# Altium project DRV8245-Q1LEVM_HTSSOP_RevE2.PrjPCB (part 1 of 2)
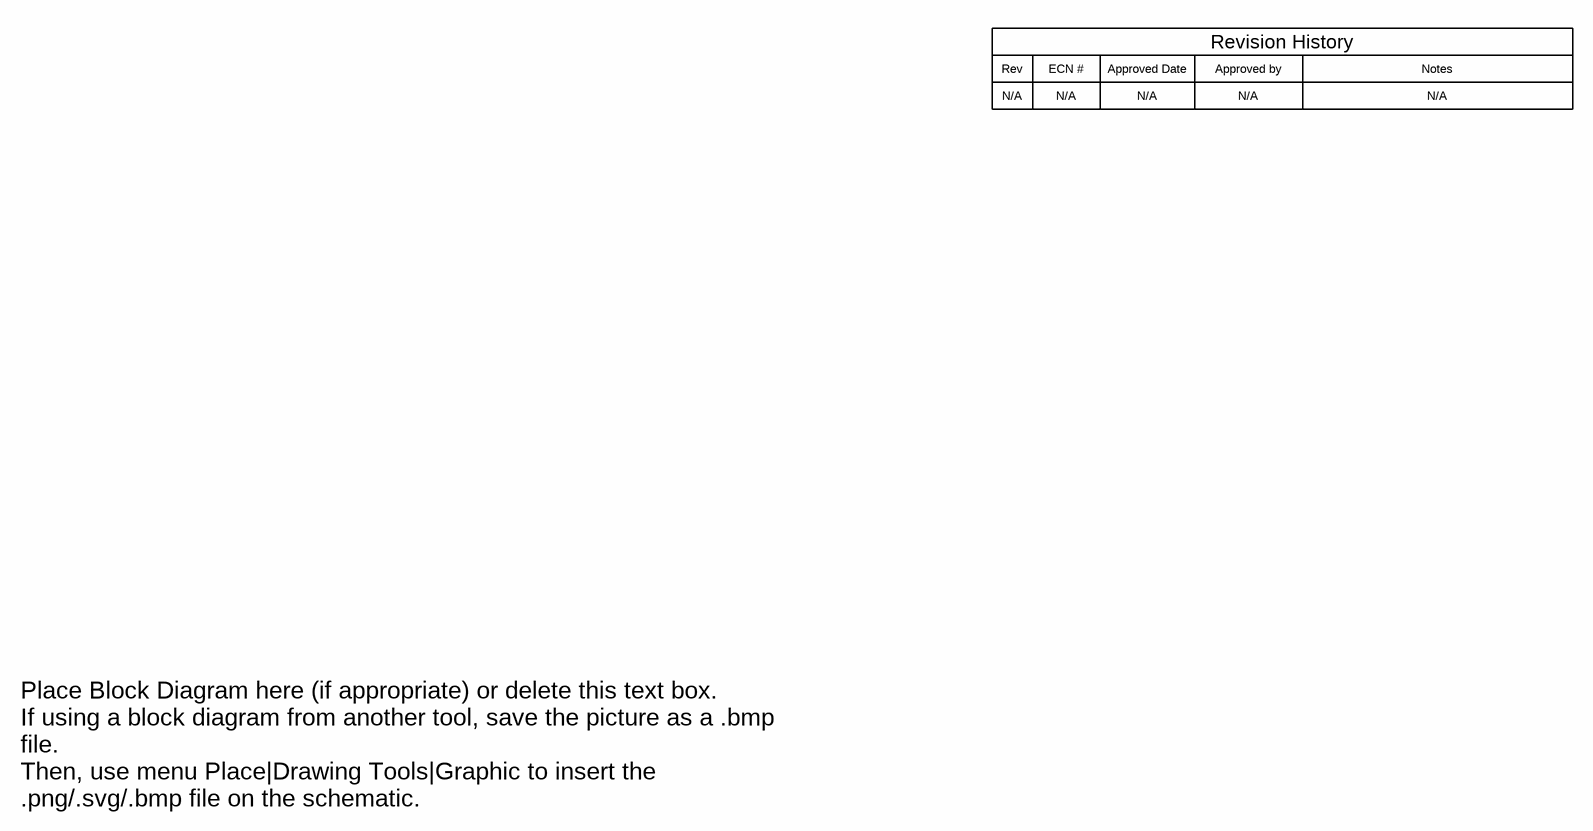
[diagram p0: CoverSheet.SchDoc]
CopyrightYear: 2020; PCB_Layout: Michael Erdahl; PCB_Rev: E2; PRJ_Customer: Public Release; PRJ_Engineer: Michael Erdahl; PRJ_Number: MD048; PRJ_Title: DRV8245S/H-Q1EVM HTSSOP; SCH_Rev: E2; TechSupport: http://www.ti.com/support; TID: N/A
4 sheets, 194 parts. Net scope: global (net labels, ports and power ports of the same name join across sheets).
Board file: DRV8245-Q1LEVM_HTSSOP_RevE2.PcbDoc
Sheets:
  CoverSheet.SchDoc
  Hardware.SchDoc
  DRV8245-Q1LEVM_HTSSOP_RevE2.SchDoc
  ezFET.SchDoc

## Sheet CoverSheet.SchDoc
size 431 x 279 mm; Date: Not shown in title block; ApprovedBy: Not shown in title block; CheckedBy: Not shown in title block; Author: Not shown in title block; CompanyName: Not shown in title block; Engineer: Not shown in title block; Organization: Not shown in title block; Address1: Not shown in title block; Address2: Not shown in title block; Address3: Not shown in title block; Address4: Not shown in title block; DocumentNumber: 1; Revision: Use project parameter SCH_Rev; SheetNumber: 1; SheetTotal: 3; PageSetup: Record=PageOptions¦CenterHorizontal=True¦CenterVertical=True¦PrintScale=1.00¦XCorrection=1.00¦YCorrection=1.00¦PrintKind=0¦BorderSize=5000000¦LeftOffset=0¦BottomOffset=0¦Orientation=2¦PaperLength=1000¦PaperWidth=1000¦Scale=100¦PaperSource=15¦PrintQuality=600¦MediaType=1¦DitherType=10¦PaperKind=Letter¦PrintScaleMode=1

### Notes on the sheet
- Rev
- N/A
- ECN #
- Approved Date
- Approved by
- Revision History
- Notes
- Place Block Diagram here (if appropriate) or delete this text box.
  If using a block diagram from another tool, save the picture as a .bmp file.
  Then, use menu Place|Drawing Tools|Graphic to insert the .png/.svg/.bmp file on the schematic.

## Sheet Hardware.SchDoc
size 431 x 279 mm; Date: Not shown in title block; ApprovedBy: Not shown in title block; CheckedBy: Not shown in title block; Author: Not shown in title block; CompanyName: Not shown in title block; Engineer: Not shown in title block; Organization: Not shown in title block; Address1: Not shown in title block; Address2: Not shown in title block; Address3: Not shown in title block; Address4: Not shown in title block; DocumentNumber: 3; Revision: Use project parameter SCH_Rev; SheetNumber: 3; SheetTotal: 3; PageSetup: Record=PageOptions¦CenterHorizontal=True¦CenterVertical=True¦PrintScale=1.00¦XCorrection=1.00¦YCorrection=1.00¦PrintKind=0¦BorderSize=5000000¦LeftOffset=0¦BottomOffset=0¦Orientation=2¦PaperLength=1000¦PaperWidth=1000¦Scale=100¦PaperSource=15¦PrintQuality=600¦MediaType=1¦DitherType=10¦PaperKind=Letter¦PrintScaleMode=1
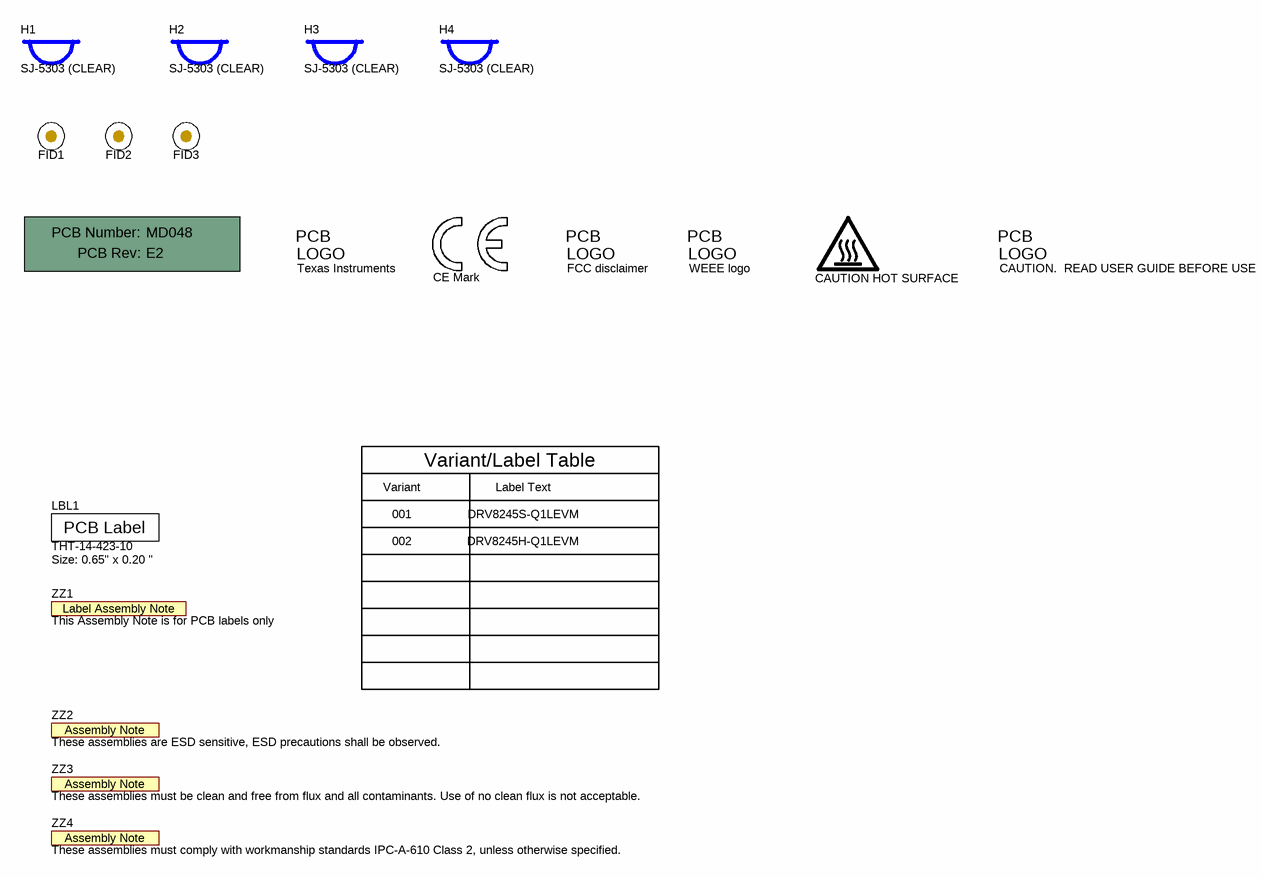
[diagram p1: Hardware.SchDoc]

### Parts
!PCB1  Printed Circuit Board  (value not drawn)  (mechanical)
FID1  Fiducial  [Fiducial10-20]  (value not drawn)
FID2  Fiducial  [Fiducial10-20]  (value not drawn)
FID3  Fiducial  [Fiducial10-20]  (value not drawn)
H1  SJ-5303 (CLEAR)  [Bumpon_SJ5003Transparent]
H2  SJ-5303 (CLEAR)  [Bumpon_SJ5003Transparent]
H3  SJ-5303 (CLEAR)  [Bumpon_SJ5003Transparent]
H4  SJ-5303 (CLEAR)  [Bumpon_SJ5003Transparent]
LBL1  THT-14-423-10  Note: Size: 0.65" x 0.20 "  [Label_650x200]
Logo1  CE Mark  [CE_Mark_5mm]  (no BOM)
Logo2  Texas Instruments  [TI_Stacked_Overlay_Small]  (no BOM)
Logo3  FCC disclaimer  [FCC_disclaimer]  (no BOM)
Logo4  WEEE logo  [WEEE_Minimum]  (no BOM)
Logo5  CAUTION.  READ USER GUIDE BEFORE USE  [IEC_Caution_Small]  (no BOM)
LOGO6  CAUTION HOT SURFACE  [IEC_HotSurface_Small]  (no BOM)
ZZ1  This Assembly Note is for PCB labels only  [AssemblyNoteLabel]  (no BOM)
ZZ2  These assemblies are ESD sensitive, ESD precautions shall be observed.  [AssemblyNote]  (no BOM)
ZZ3  These assemblies must be clean and free from flux and all contaminants. Use of no clean flux is not acceptable.  [AssemblyNote]  (no BOM)
ZZ4  These assemblies must comply with workmanship standards IPC-A-610 Class 2, unless otherwise specified.  [AssemblyNote]  (no BOM)

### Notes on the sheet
- Variant
- Variant/Label Table
- Label Text
- 001
- 002
- DRV8245S-Q1LEVM
- DRV8245H-Q1LEVM

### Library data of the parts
!PCB1 = CMP-0003618-2: Manufacturer: Any; PartNumber: MD048
FID1-FID3 = CMP-0077181-1: Fiducial mark.  There is nothing to buy or mount.
H1-H4 = CMP-0003620-1: Bumpon, Hemisphere, 0.44 X 0.20, Clear; Manufacturer: 3M
LBL1 = CMP-0003625-1: Thermal Transfer Printable Labels, 0.650" W x 0.200" H - 10,000 per roll; Manufacturer: Brady; CompType: Label
Logo1 = CMP-0074844-1: SymbolCreator: a0412235
Logo2 = CMP-0074838-1: Texas Instrument Corporate Signature; SymbolCreator: a0412235; Lib Reference: TI_Logo; Library Reference: Logo
Logo3 = CMP-0074847-1: FCC_disclaimer; Library Reference: Logo
Logo4 = CMP-0074769-1
Logo5 = CMP-0074836-1: IEC 61010-1 Caution Warning; SymbolCreator: a0412235; Lib Reference: IEC_Caution
LOGO6 = CMP-0074837-1: IEC 61010-1 Hot Surface Warning; SymbolCreator: a0412235
ZZ1 = CMP-0003616-3
ZZ2 = CMP-0077236-1
ZZ3 = CMP-0077237-1
ZZ4 = CMP-0077238-1

## Sheet DRV8245-Q1LEVM_HTSSOP_RevE2.SchDoc
size 431 x 279 mm; Date: Not shown in title block; ApprovedBy: Not shown in title block; CheckedBy: Not shown in title block; Author: Not shown in title block; CompanyName: Not shown in title block; Engineer: Not shown in title block; Organization: Not shown in title block; Address1: Not shown in title block; Address2: Not shown in title block; Address3: Not shown in title block; Address4: Not shown in title block; DocumentNumber: 2; Revision: Use project parameter SCH_Rev; SheetNumber: 2; SheetTotal: 3; PageSetup: Record=PageOptions¦CenterHorizontal=True¦CenterVertical=True¦PrintScale=1.00¦XCorrection=1.00¦YCorrection=1.00¦PrintKind=0¦BorderSize=5000000¦LeftOffset=0¦BottomOffset=0¦Orientation=2¦PaperLength=1000¦PaperWidth=1000¦Scale=100¦PaperSource=15¦PrintQuality=600¦MediaType=1¦DitherType=10¦PaperKind=Letter¦PrintScaleMode=1
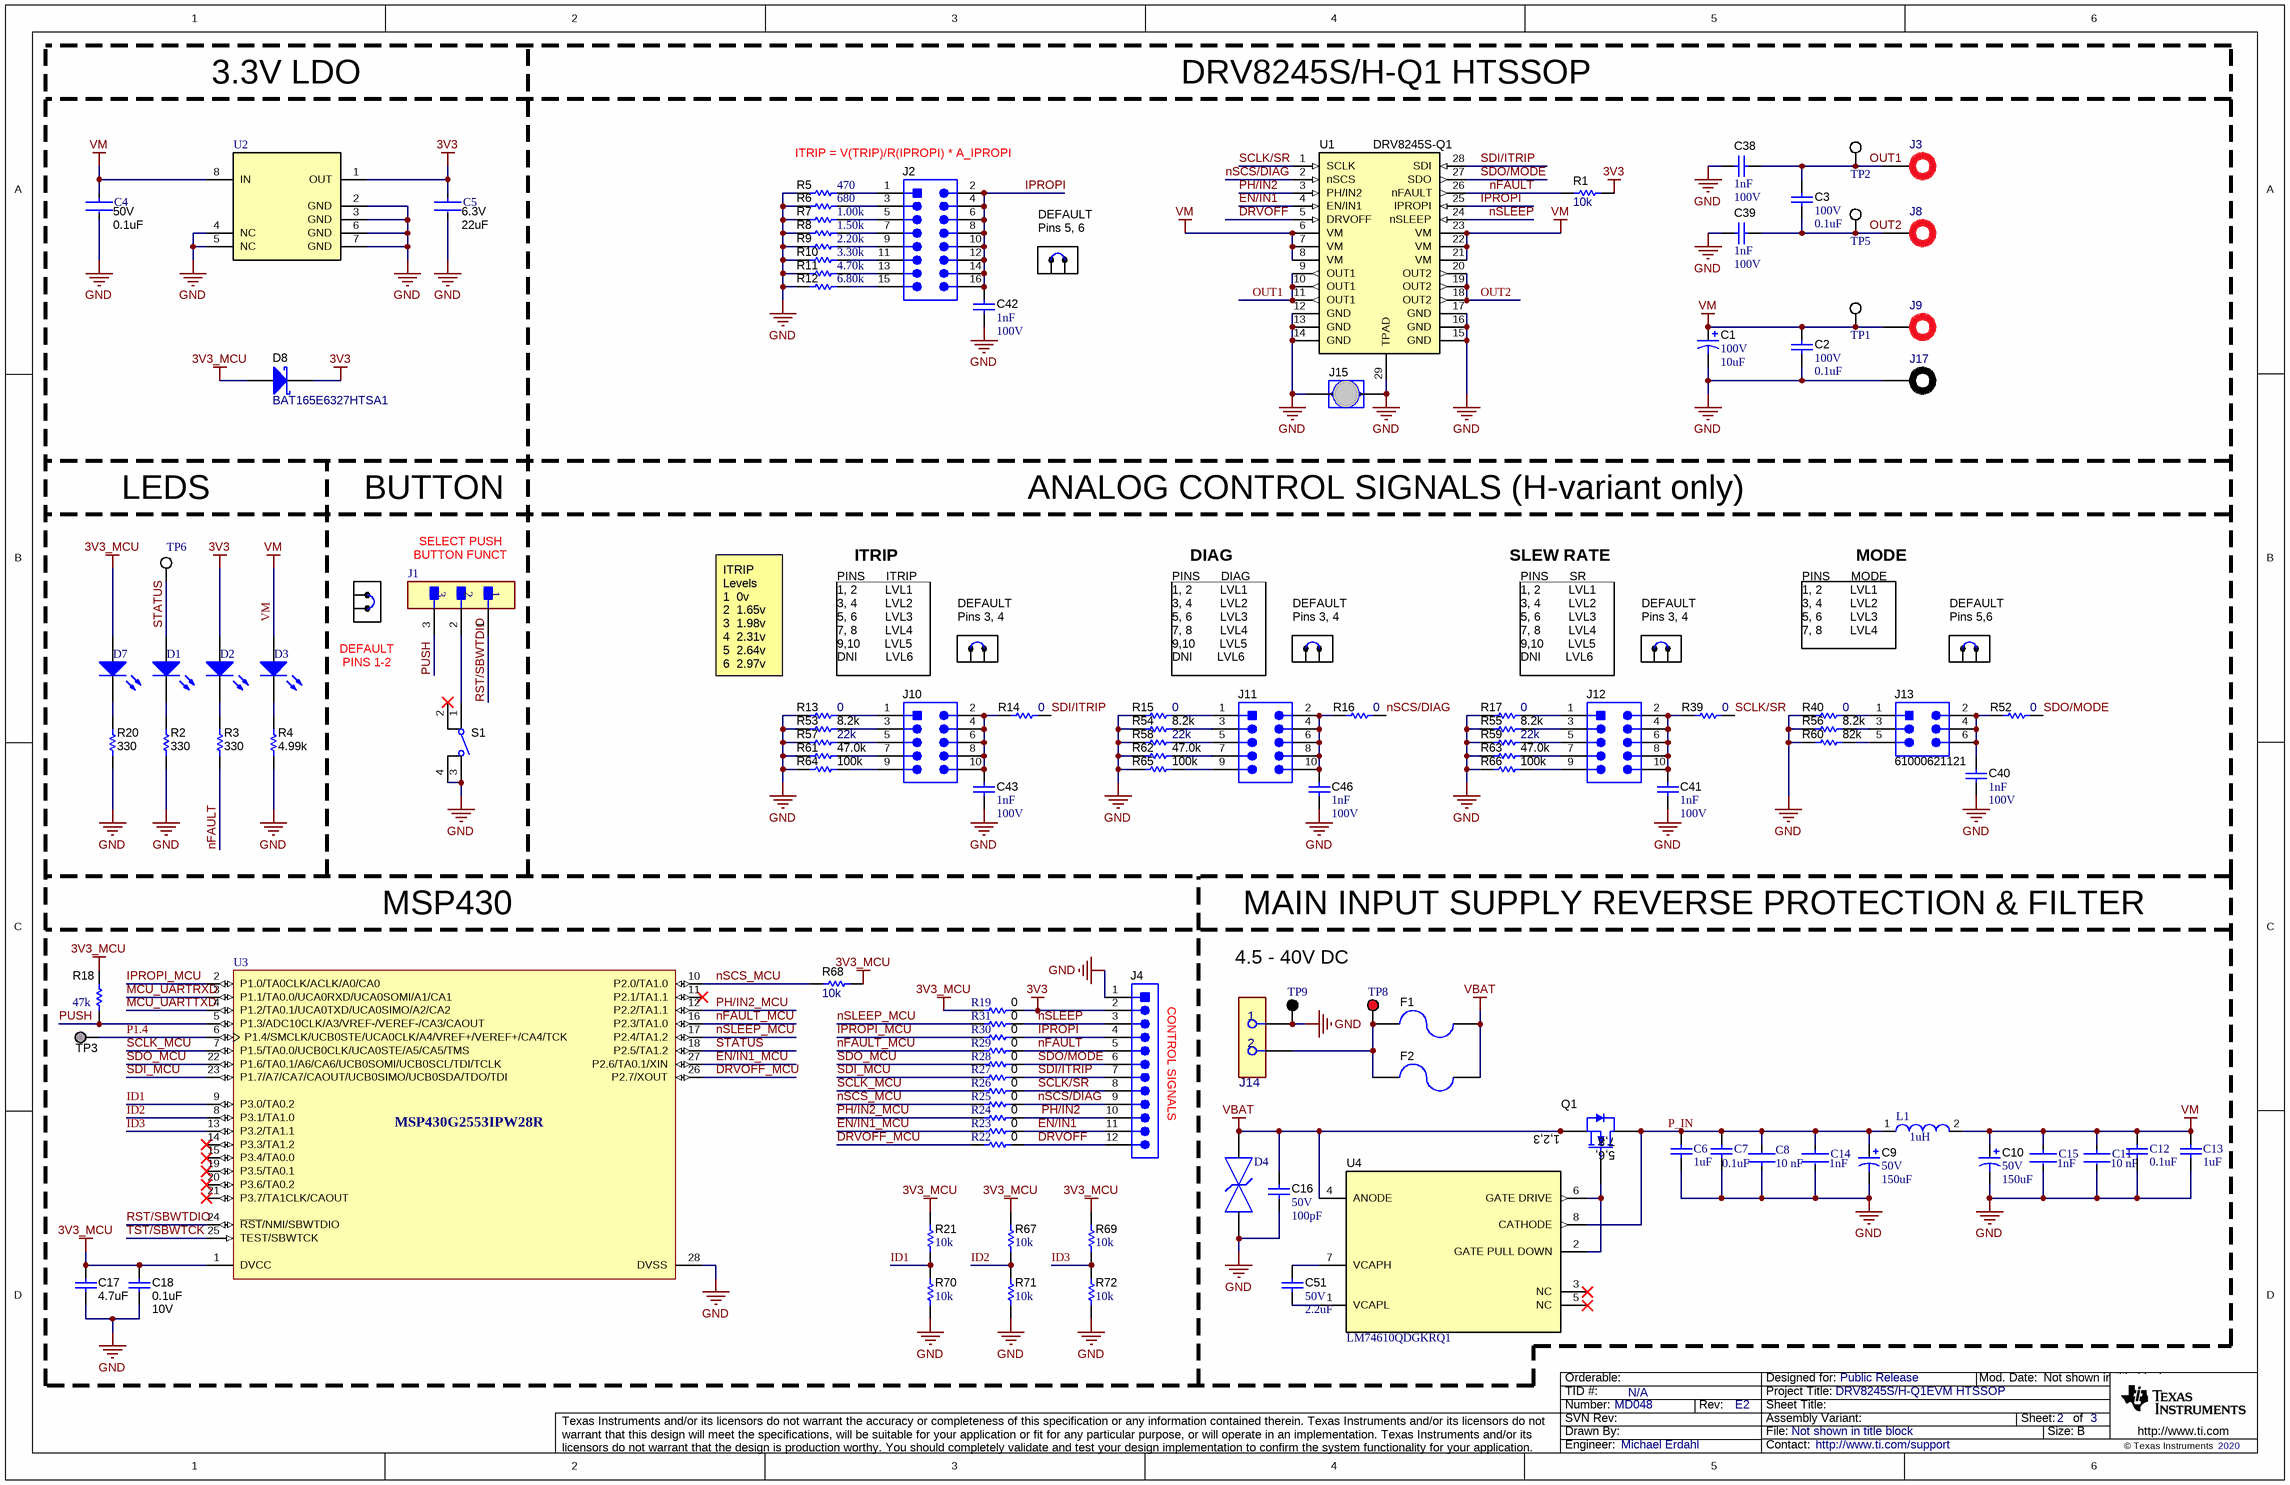
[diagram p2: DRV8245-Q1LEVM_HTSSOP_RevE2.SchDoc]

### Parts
C1  VDC_V: 100V  ValueDisplayed: 10uF  [SM_RADIAL_E]  (hidden comment: EEE-2AA100UP)
C2  VDC_V: 100V  ValueDisplayed: 0.1uF  [1206_180]  (hidden comment: C3216X7R2A104K160AA)
C3  VDC_V: 100V  ValueDisplayed: 0.1uF  [1206_180]  (hidden comment: C3216X7R2A104K160AA)
C4  value 0.1uF  Voltage Rating: 50V  [FP-CL10-0_1-MFG]  (hidden comment: CL10B104JB8NNNC)
C5  Voltage Rating: 6.3V  Capacitance: 22uF  [FP-CL10-IPC_A]  (hidden comment: CL10A226MQ8NUNE)
C6  1uF  [CAPC2013X135X45LL10T25]
C7  0.1uF  [CAPC0603(1608)100_L]
C8  value 10 nF  [FP-CC0603-DA-MFG]  (hidden comment: CC0603KPX7R9BB103)
C9  VDC_V: 50V  ValueDisplayed: 150uF  [SM_RADIAL_G]  (hidden comment: EEE-FK1H151P)
C10  VDC_V: 50V  ValueDisplayed: 150uF  [SM_RADIAL_G]  (hidden comment: EEE-FK1H151P)
C11  value 10 nF  [FP-CC0603-DA-MFG]  (hidden comment: CC0603KPX7R9BB103)
C12  0.1uF  [CAPC0603(1608)100_L]
C13  1uF  [CAPC2013X135X45LL10T25]
C14  1nF  [FP-C0603C-CF-MFG]
C15  1nF  [FP-C0603C-CF-MFG]
C16  VDC_V: 50V  ValueDisplayed: 100pF  [0805_HV]  (hidden comment: 08055A101JAT2A)
C17  ValueDisplayed: 4.7uF  [0402_065L]  (hidden comment: Capacitor)
C18  ValueDisplayed: 0.1uF  VDC_V: 10V  [0603L]  (hidden comment: 885012206020)
C38  Cap_F: 1nF  VDC_V: 100V  [0603]  (hidden comment: CGA3E2X7R2A102K080AA)
C39  Cap_F: 1nF  VDC_V: 100V  [0603]  (hidden comment: CGA3E2X7R2A102K080AA)
C40  Cap_F: 1nF  VDC_V: 100V  [0603]  (hidden comment: CGA3E2X7R2A102K080AA)
C41  Cap_F: 1nF  VDC_V: 100V  [0603]  (hidden comment: CGA3E2X7R2A102K080AA)
C42  Cap_F: 1nF  VDC_V: 100V  [0603]  (hidden comment: CGA3E2X7R2A102K080AA)
C43  Cap_F: 1nF  VDC_V: 100V  [0603]  (hidden comment: CGA3E2X7R2A102K080AA)
C46  Cap_F: 1nF  VDC_V: 100V  [0603]  (hidden comment: CGA3E2X7R2A102K080AA)
C51  VDC_V: 50V  ValueDisplayed: 2.2uF  [0805_HV]  (hidden comment: C2012X5R1H225K125AB)
D1  150080VS75000  [0805_A]  (value not drawn)
D2  150080SS75000  [0805_A]  (value not drawn)
D3  150080VS75000  [0805_A]  (value not drawn)
D4  SMAJ36CA  [FP-SMAJ-CA-MFG]  (value not drawn)
D7  150080VS75000  [0805_A]  (value not drawn)
D8  BAT165E6327HTSA1  [SOD-323]
F1  0463030.ER  [Fuse_0463]  (value not drawn)
F2  0463030.ER  [Fuse_0463]  (value not drawn)
J1  PR20203VBNN  [FP-PR20203VBNN-MFG]  (value not drawn)
J2  TSM-108-01-L-DV  [Samtec_TSM-108-01-x-DV]  (value not drawn)
J3  CT3151SP-2  [CTE_CT3151SP-2]  (value not drawn)
J4  PBC12SABN  [Sullins_PxC12SABN]  (value not drawn)
J8  CT3151SP-2  [CTE_CT3151SP-2]  (value not drawn)
J9  CT3151SP-2  [CTE_CT3151SP-2]  (value not drawn)
J10  TSM-105-01-L-DV-P  [Samtec_TSM-105-01-x-DV]  (value not drawn)
J11  TSM-105-01-L-DV-P  [Samtec_TSM-105-01-x-DV]  (value not drawn)
J12  TSM-105-01-L-DV-P  [Samtec_TSM-105-01-x-DV]  (value not drawn)
J13  61000621121  [Wurth_61000621121]
J14  691256610002  [FP-691256610002_HDR2-MFG]  (value not drawn)
J15  D3082-05  [Harwin_D3082-05]  (value not drawn)
J17  CT3151SP-0  [CTE_CT3151SP-0]  (value not drawn)
L1  1uH  [WE-HCC-1210]
Q1  CSD18513Q5A  [DQJ0008A]  (value not drawn)
R1  ValueDisplayed: 10k  [0603]  (hidden comment: RC0603JR-0710KL)
R2  ValueDisplayed: 330  [0603L]  (hidden comment: CMP-0025785-4)
R3  ValueDisplayed: 330  [0603L]  (hidden comment: CMP-0025785-4)
R4  ValueDisplayed: 4.99k  [0603L]  (hidden comment: CRCW06034K99FKEAC)
R5  ValueDisplayed: 470  [0603]  (hidden comment: RC0603FR-07470RL)
R6  ValueDisplayed: 680  [0603]  (hidden comment: RC0603FR-07680RL)
R7  ValueDisplayed: 1.00k  [0603]  (hidden comment: RC0603FR-071KL)
R8  ValueDisplayed: 1.50k  [0603]  (hidden comment: RC0603FR-071K5L)
R9  ValueDisplayed: 2.20k  [0603]  (hidden comment: RC0603FR-072K2L)
R10  ValueDisplayed: 3.30k  [0603]  (hidden comment: RC0603FR-073K3L)
R11  ValueDisplayed: 4.70k  [0603]  (hidden comment: RC0603FR-074K7L)
R12  ValueDisplayed: 6.80k  [0603]  (hidden comment: RC0603FR-076K8L)
R13  ValueDisplayed: 0  [0603]  (hidden comment: PMR03EZPJ000)
R14  ValueDisplayed: 0  [0603]  (hidden comment: PMR03EZPJ000)
R15  ValueDisplayed: 0  [0603]  (hidden comment: PMR03EZPJ000)
R16  ValueDisplayed: 0  [0603]  (hidden comment: PMR03EZPJ000)
R17  ValueDisplayed: 0  [0603]  (hidden comment: PMR03EZPJ000)
R18  ValueDisplayed: 47k  [0603]  (hidden comment: RC0603JR-0747KL)
R19  value 0  [RESC1609X55X30NL10T20]  (hidden comment: CRCW06030000Z0EAHP)
R20  ValueDisplayed: 330  [0603L]  (hidden comment: CMP-0025785-4)
R21  ValueDisplayed: 10k  [0603]  (hidden comment: RC0603JR-0710KL)
R22  value 0  [RESC1609X55X30NL10T20]  (hidden comment: CRCW06030000Z0EAHP)
R23  value 0  [RESC1609X55X30NL10T20]  (hidden comment: CRCW06030000Z0EAHP)
R24  value 0  [RESC1609X55X30NL10T20]  (hidden comment: CRCW06030000Z0EAHP)
R25  value 0  [RESC1609X55X30NL10T20]  (hidden comment: CRCW06030000Z0EAHP)
R26  value 0  [RESC1609X55X30NL10T20]  (hidden comment: CRCW06030000Z0EAHP)
R27  value 0  [RESC1609X55X30NL10T20]  (hidden comment: CRCW06030000Z0EAHP)
R28  value 0  [RESC1609X55X30NL10T20]  (hidden comment: CRCW06030000Z0EAHP)
R29  value 0  [RESC1609X55X30NL10T20]  (hidden comment: CRCW06030000Z0EAHP)
R30  value 0  [RESC1609X55X30NL10T20]  (hidden comment: CRCW06030000Z0EAHP)
R31  value 0  [RESC1609X55X30NL10T20]  (hidden comment: CRCW06030000Z0EAHP)
R39  ValueDisplayed: 0  [0603]  (hidden comment: PMR03EZPJ000)
R40  ValueDisplayed: 0  [0603]  (hidden comment: PMR03EZPJ000)
R52  ValueDisplayed: 0  [0603]  (hidden comment: PMR03EZPJ000)
R53  ValueDisplayed: 8.2k  [0603]  (hidden comment: CRCW06038K20JNEA)
R54  ValueDisplayed: 8.2k  [0603]  (hidden comment: CRCW06038K20JNEA)
R55  ValueDisplayed: 8.2k  [0603]  (hidden comment: CRCW06038K20JNEA)
R56  ValueDisplayed: 8.2k  [0603]  (hidden comment: CRCW06038K20JNEA)
R57  ValueDisplayed: 22k  [0603]  (hidden comment: CRCW060322K0JNEA)
R58  ValueDisplayed: 22k  [0603]  (hidden comment: CRCW060322K0JNEA)
R59  ValueDisplayed: 22k  [0603]  (hidden comment: CRCW060322K0JNEA)
R60  ValueDisplayed: 82k  [0603]  (hidden comment: CRCW060382K0JNEA)
R61  ValueDisplayed: 47.0k  [0603]  (hidden comment: CRCW060347K0FKEA)
R62  ValueDisplayed: 47.0k  [0603]  (hidden comment: CRCW060347K0FKEA)
R63  ValueDisplayed: 47.0k  [0603]  (hidden comment: CRCW060347K0FKEA)
R64  ValueDisplayed: 100k  [0603]  (hidden comment: CRCW0603100KDHEAP)
R65  ValueDisplayed: 100k  [0603]  (hidden comment: CRCW0603100KDHEAP)
R66  ValueDisplayed: 100k  [0603]  (hidden comment: CRCW0603100KDHEAP)
R67  ValueDisplayed: 10k  [0603]  (hidden comment: RC0603JR-0710KL)
R68  ValueDisplayed: 10k  [0603]  (hidden comment: RC0603JR-0710KL)
R69  ValueDisplayed: 10k  [0603]  (hidden comment: RC0603JR-0710KL)
R70  ValueDisplayed: 10k  [0603]  (hidden comment: RC0603JR-0710KL)
R71  ValueDisplayed: 10k  [0603]  (hidden comment: RC0603JR-0710KL)
R72  ValueDisplayed: 10k  [0603]  (hidden comment: RC0603JR-0710KL)
S1  FSM4JSMA  [SW_FSM4JSMA]  (value not drawn)
SH-J1  881545-2  [TE_881545-2]  (value not drawn)
SH-J2  60900213421  [Wurth_60900213421]  (value not drawn)
SH-J3  60900213421  [Wurth_60900213421]  (value not drawn)
SH-J4  60900213421  [Wurth_60900213421]  (value not drawn)
SH-J5  60900213421  [Wurth_60900213421]  (value not drawn)
SH-J6  60900213421  [Wurth_60900213421]  (value not drawn)
TP1  5015  [Testpoint_Keystone_Miniature]  (value not drawn)
TP2  5015  [Testpoint_Keystone_Miniature]  (value not drawn)
TP3  TP_H0.45P0.75  [TP_H045P075]  (value not drawn)  (no BOM)
TP5  5015  [Testpoint_Keystone_Miniature]  (value not drawn)
TP6  5015  [Testpoint_Keystone_Miniature]  (value not drawn)
TP8  5010  [Keystone5010]  (value not drawn)
TP9  5011  [Keystone5011]  (value not drawn)
U1  DRV8245S-Q1  [HTSSOP-28-epod]
U2  LM9036M-3.3/NOPB  [D0008A_N]  (value not drawn)
U3  MSP430G2553IPW28R  [PW0028A_N]
U4  LM74610QDGKRQ1  [DGK0008A_N]

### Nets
3V3: C5.1 D2.2(A) D8.1(K) J4.2 R1.2 R19.2 U2.1(OUT)
3V3_MCU: C17.1 C18.1 D7.2(A) D8.2(A) R18.2 R19.1 R21.1 R67.1 R68.1 R69.1 U3.1(DVCC)
GND: C1.2(-) C2.2 C4.2 C5.2 C6.1 C7.1 C8.1 C9.2(-) C10.2(-) C11.2 C12.1 C13.1 C14.2 C15.2 C16.2 C17.2 C18.2 C38.1 C39.1 C40.1 C41.1 C42.1 C43.1 C46.1 D4.1 J4.1 J14.1 J15.1 J15.2 J17.1 R2.1 R4.1 R5.1 R6.1 R7.1 R8.1 R9.1 R10.1 R11.1 R12.1 R13.2 R15.2 R17.2 R20.1 R40.2 R53.1 R54.1 R55.1 R56.1 R57.1 R58.1 R59.1 R60.2 R61.1 R62.1 R63.1 R64.1 R65.1 R66.1 R70.2 R71.2 R72.2 S1.3 S1.4 TP9.1 U1.12(GND) U1.13(GND) U1.14(GND) U1.15(GND) U1.16(GND) U1.17(GND) U1.29(TPAD) U2.2(GND) U2.3(GND) U2.4(NC) U2.5(NC) U2.6(GND) U2.7(GND) U3.28(DVSS)
VBAT: C16.1 D4.2 F1.1 F2.1 Q1.1(S) Q1.2(S) Q1.3(S) U4.4(ANODE)
VM: C1.1(+) C2.1 C4.1 C10.1(+) C11.1 C12.2 C13.2 C15.1 D3.2(A) J9.1 L1.2 TP1.1 U1.6(VM) U1.7(VM) U1.8(VM) U1.21(VM) U1.22(VM) U1.23(VM) U2.8(IN)
DRVOFF: J4.12 R22.2 U1.5(DRVOFF)
DRVOFF_MCU: R22.1 U3.26(P2.7/XOUT)
EN/IN1: J4.11 R23.2 U1.4(EN/IN1)
EN/IN1_MCU: R23.1 U3.27(P2.6/TA0.1/XIN)
ID1: R21.2 R70.1 U3.9(P3.0/TA0.2)
ID2: R67.2 R71.1 U3.8(P3.1/TA1.0)
ID3: R69.2 R72.1 U3.13(P3.2/TA1.1)
IPROPI: C42.2 J2.2 J2.4 J2.6 J2.8 J2.10 J2.12 J2.14 J2.16 J4.4 R30.2 U1.25(IPROPI)
IPROPI_MCU: R30.1 U3.2(P1.0/TA0CLK/ACLK/A0/CA0)
MCU_UARTRXD: U3.3(P1.1/TA0.0/UCA0RXD/UCA0SOMI/A1/CA1)
MCU_UARTTXD: U3.4(P1.2/TA0.1/UCA0TXD/UCA0SIMO/A2/CA2)
nFAULT: J4.5 R1.1 R3.1 R29.2 U1.26(nFAULT)
nFAULT_MCU: R29.1 U3.16(P2.3/TA1.0)
nSCS/DIAG: J4.9 R16.1 R25.2 U1.2(nSCS)
nSCS_MCU: R25.1 R68.2 U3.10(P2.0/TA1.0)
nSLEEP: J4.3 R31.2 U1.24(nSLEEP)
nSLEEP_MCU: R31.1 U3.17(P2.4/TA1.2)
OUT1: C3.1 C38.2 J3.1 TP2.1 U1.9(OUT1) U1.10(OUT1) U1.11(OUT1)
OUT2: C3.2 C39.2 J8.1 TP5.1 U1.18(OUT2) U1.19(OUT2) U1.20(OUT2)
P1.4: TP3.1 U3.6(P1.4/SMCLK/UCB0STE/UCA0CLK/A4/VREF+/VEREF+/CA4/TCK)
P_IN: C6.2 C7.2 C8.2 C9.1(+) C14.1 L1.1 Q1.5(D) Q1.6(D) Q1.7(D) Q1.8(D) Q1.9(D) U4.8(CATHODE)
PH/IN2: J4.10 R24.2 U1.3(PH/IN2)
PH/IN2_MCU: R24.1 U3.12(P2.2/TA1.1)
PUSH: J1.3 R18.1 U3.5(P1.3/ADC10CLK/A3/VREF-/VEREF-/CA3/CAOUT)
RST/SBWTDIO: J1.1 U3.24(~{RST}/NMI/SBWTDIO)
SCLK/SR: J4.8 R26.2 R39.1 U1.1(SCLK)
SCLK_MCU: R26.1 U3.7(P1.5/TA0.0/UCB0CLK/UCA0STE/A5/CA5/TMS)
SDI/ITRIP: J4.7 R14.1 R27.2 U1.28(SDI)
SDI_MCU: R27.1 U3.23(P1.7/A7/CA7/CAOUT/UCB0SIMO/UCB0SDA/TDO/TDI)
SDO/MODE: J4.6 R28.2 R52.1 U1.27(SDO)
SDO_MCU: R28.1 U3.22(P1.6/TA0.1/A6/CA6/UCB0SOMI/UCB0SCL/TDI/TCLK)
STATUS: D1.2(A) TP6.1 U3.18(P2.5/TA1.2)
TST/SBWTCK: U3.25(TEST/SBWTCK)
NetC40_2: C40.2 J13.2 J13.4 J13.6 R52.2
NetC41_2: C41.2 J12.2 J12.4 J12.6 J12.8 J12.10 R39.2
NetC43_2: C43.2 J10.2 J10.4 J10.6 J10.8 J10.10 R14.2
NetC46_2: C46.2 J11.2 J11.4 J11.6 J11.8 J11.10 R16.2
NetC51_1: C51.1 U4.7(VCAPH)
NetC51_2: C51.2 U4.1(VCAPL)
NetD1_1: D1.1(K) R2.2
NetD2_1: D2.1(K) R3.2
NetD3_1: D3.1(K) R4.2
NetD7_1: D7.1(K) R20.2
NetF1_2: F1.2 F2.2 J14.2 TP8.1
NetJ1_2: J1.2 S1.1
NetJ2_1: J2.1 R5.2
NetJ2_3: J2.3 R6.2
NetJ2_5: J2.5 R7.2
NetJ2_7: J2.7 R8.2
NetJ2_9: J2.9 R9.2
NetJ2_11: J2.11 R10.2
NetJ2_13: J2.13 R11.2
NetJ2_15: J2.15 R12.2
NetJ10_1: J10.1 R13.1
NetJ10_3: J10.3 R53.2
NetJ10_5: J10.5 R57.2
NetJ10_7: J10.7 R61.2
NetJ10_9: J10.9 R64.2
NetJ11_1: J11.1 R15.1
NetJ11_3: J11.3 R54.2
NetJ11_5: J11.5 R58.2
NetJ11_7: J11.7 R62.2
NetJ11_9: J11.9 R65.2
NetJ12_1: J12.1 R17.1
NetJ12_3: J12.3 R55.2
NetJ12_5: J12.5 R59.2
NetJ12_7: J12.7 R63.2
NetJ12_9: J12.9 R66.2
NetJ13_1: J13.1 R40.1
NetJ13_3: J13.3 R56.2
NetJ13_5: J13.5 R60.1
NetQ1_4: Q1.4(G) U4.2(GATE_PULL_DOWN) U4.6(GATE_DRIVE)

Not connected (* = marked no-connect by the designer): S1 2*; U3 11(P2.1/TA1.1)* 14(P3.3/TA1.2)* 15(P3.4/TA0.0)* 19(P3.5/TA0.1)* 20(P3.6/TA0.2)* 21(P3.7/TA1CLK/CAOUT)*; U4 3(NC)* 5(NC)*

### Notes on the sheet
- 3.3V LDO
- DRV8245S/H-Q1 HTSSOP
- ITRIP = V(TRIP)/R(IPROPI) * A_IPROPI
- (near SH-J6) DEFAULT
  Pins 5, 6
- LEDS
- BUTTON
- ANALOG CONTROL SIGNALS (H-variant only)
- SELECT PUSH
- BUTTON FUNCT
- ITRIP
- DIAG
- SLEW RATE
- MODE
- PINS      ITRIP
- (near SH-J3) DEFAULT
  Pins 3, 4
- PINS      DIAG
- (near SH-J4) DEFAULT
  Pins 3, 4
- PINS      SR
- (near SH-J5) DEFAULT
  Pins 3, 4
- PINS      MODE
- (near SH-J2) DEFAULT
  Pins 5,6
- (near SH-J1) DEFAULT
- PINS 1-2
- ITRIP Levels
  1  0v
  2  1.65v
  3  1.98v
  4  2.31v
  5  2.64v
  6  2.97v
- 1, 2        LVL1
  3, 4        LVL2
  5, 6        LVL3
  7, 8        LVL4
  9,10       LVL5
  DNI        LVL6
- 1, 2        LVL1
  3, 4        LVL2
  5, 6        LVL3
  7, 8        LVL4
  9,10       LVL5
  DNI       LVL6
- 1, 2        LVL1
  3, 4        LVL2
  5, 6        LVL3
  7, 8        LVL4
- MSP430
- MAIN INPUT SUPPLY REVERSE PROTECTION & FILTER
- 4.5 - 40V DC
- (near J4) CONTROL SIGNALS

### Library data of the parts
C1 = CMP-0011164-2: CAP, AL, 10 uF, 100 V, +/- 20%, AEC-Q200 Grade 3, SMD; Manufacturer: Panasonic; TaMin_C: -40°C; Polarized: Y; SizeAreaWB_mm2: 118.45; Value1: Unknown; U/M: EA; Value: 10uF; TaMax_C: 85°C; SizeZ_mm: 6.2; SizeX_mm: 9.5; SizeY_mm: 8.3; Cap_Case: 8.0x6.0mm; SizeArea_mm2: 78.85; CompType: Capacitor; Cap_F: 10µF; IRMS_A: 50mA; AEC Grade: 3; AEC Category: Q200
C2 C3 = CMP-0008709-1: CAP, CERM, 0.1 uF, 100 V, +/- 10%, X7R, 1206; Manufacturer: TDK; TaMin_C: -55°C; ESR_ohm: 0.030343; Polarized: N; SizeAreaWB_mm2: 10.92; Value1: 0.030343 ohm; U/M: EA; Value: 0.1uF; TaMax_C: 125°C; SizeZ_mm: 1.8; SizeX_mm: 3.2; SizeY_mm: 1.6; SizeArea_mm2: 5.12; Cap_F: 100nF; IRMS_A: 1.33802A; AEC Category: Q200
C4 = CMP-13271-000011-1: CAP CER 0.1UF 50V X7R 0603; Manufacturer: Samsung Electro-Mechanics America, Inc; Material: Ceramic; Temperature Coefficient: 15%; Tolerance: 5%; Capacitance: 100nF
C5 = CMP-13271-003053-1: Cap Ceramic 22uF 6.3V X5R ±20% Pad SMD 0603 +85°C T/R
C6 C13 = CMP-2007-03579-1: GRM21BR71H105KA12L; Manufacturer: Murata
C7 C12 = CMP-1035-02591-1: CAP 100nF 50V ±5% 0603 (1608 Metric) Thickness 1mm SMD; Tolerance: Â±5%; Case-Metric: 1608; Case-EIA: 0603
C8 C11 = CMP-1035-02321-3: CAP CER 10000PF 50V X7R 0603; Manufacturer: YAGEO; Tolerance: 0.1; Material: Ceramic; Temperature Coefficient: 15%
C9 C10 = CMP-0011178-2: CAP, AL, 150 uF, 50 V, +/- 20%, 0.18 ohm, AEC-Q200 Grade 2, SMD; Manufacturer: Panasonic; TaMin_C: -55°C; ESR_ohm: 0.18; Polarized: Y; SizeAreaWB_mm2: 172.2; U/M: EA; Value: 150uF; TaMax_C: 105°C; SizeZ_mm: 10.2; SizeX_mm: 12; SizeY_mm: 10.3; Cap_Case: G; SizeArea_mm2: 123.6; CompType: Capacitor; Cap_F: 150µF; IRMS_A: 670mA; AEC Grade: 2; AEC Category: Q200
C14 C15 = CMP-03020-030804-1: CAP CER 1000PF 50V X7R 0603; Manufacturer Part Number: C0603C102J5RACAUTO; Manufacturer: KEMET; Material: Ceramic; Value: 1,000 pF; Temperature Coefficient: 30ppm/°C; Automotive Grade: Grade 1; Tolerance: 0.05
C16 = CMP-0007580-1: CAP, CERM, 100 pF, 50 V, +/- 5%, C0G/NP0, 0805; Manufacturer: AVX; TaMin_C: -55°C; ESR_ohm: 0.356; Polarized: N; SizeAreaWB_mm2: 6.75; Value1: 0.356 ohm; U/M: EA; Value: 100pF; TaMax_C: 125°C; SizeZ_mm: 1.45; SizeX_mm: 2; SizeY_mm: 1.25; Cap_Case: 0805; SizeArea_mm2: 2.5; AEC Category: Q200
C17 = CMP-0006268-2: CAP, CERM, 4.7 uF, 10 V, +/- 10%, X5R, 0402; PartNumber: C1005X5R1A475K050BC; Manufacturer: TDK; Polarized: N; Value: 4.7uF; U/M: EA; Cap_F: 4.7µF; ESR_ohm: 3.417m; Value1: 0.003417 ohm; VDC_V: 10V; IRMS_A: 2.7063A; TaMin_C: -55°C; TaMax_C: 85°C; Cap_Case: 0402_065; AEC Category: Q200; SizeArea_mm2: 0.5; SizeAreaWB_mm2: 3; SizeX_mm: 1; SizeZ_mm: 0.65
C18 = CMP-0064931-4: CAP, CERM, 0.1 uF, 10 V,+/- 10%, X7R, 0603; Manufacturer: Wurth Elektronik; Polarized: N; CompType: Capacitor; Value: 0.1uF; U/M: EA; Cap_F: 100nF; Value1: Unknown; TaMin_C: -55°C; TaMax_C: 125°C; Cap_Case: 0603; AEC Category: Q200; SizeArea_mm2: 1.28; SizeAreaWB_mm2: 4.68; SizeX_mm: 1.6; SizeY_mm: 0.8; SizeZ_mm: 1
C38-C43 C46 = CMP-0007081-4: CAP, CERM, 1000 pF, 100 V, +/- 10%, X7R, AEC-Q200 Grade 1, 0603; Manufacturer: TDK; TaMin_C: -55°C; ESR_ohm: 1.97137; Polarized: N; SizeAreaWB_mm2: 4.68; Value1: 1.97137 ohm; U/M: EA; Value: 1000pF; TaMax_C: 125°C; SizeZ_mm: 1; SizeX_mm: 1.6; SizeY_mm: 0.8; SizeArea_mm2: 1.28; AEC Qualified: Y; IRMS_A: 305.705mA; AEC Category: Q200
C51 = CMP-0007836-1: CAP, CERM, 2.2 uF, 50 V, +/- 10%, X5R, 0805; Manufacturer: TDK; TaMin_C: -55°C; ESR_ohm: 3.66m; Polarized: N; SizeAreaWB_mm2: 6.75; Value1: 0.00366 ohm; U/M: EA; Value: 2.2uF; TaMax_C: 85°C; SizeZ_mm: 1.45; SizeX_mm: 2; SizeY_mm: 1.25; Cap_Case: 0805; SizeArea_mm2: 2.5; Cap_F: 2.2µF; IRMS_A: 3.41207A; AEC Category: Q200
D1 D3 D7 = CMP-1426-00009-1: SMD mono-color Chip LED, WL-SMCW, Bright Green; Manufacturer: Wuerth Elektronik
D2 = CMP-1426-00010-1: SMD mono-color Chip LED, WL-SMCW, Super Red; Manufacturer: Wuerth Elektronik
D4 = CMP-08607-000009-1: TVS DIODE 36V 58.1V DO214AC; Manufacturer: Littelfuse Inc; Peak Pulse Power: 400W; Max Junction Temp: +150°C; Direction: Bidirectional; Peak Pulse Current: 6.9A; Number Of Channels: 1; Breakdown Voltage: 40V
D8 = CMP-0028882-1: Diode, Schottky, 40 V, 0.75 A, AEC-Q101, SOD-323; Manufacturer: Infineon Technologies; Io_A: 750mA; Green_Lifecycle: Not Set; SizeAreaWB_mm2: 8.695; Vr_V: 40V; Green_REACh: Incomplete; Value1: 0.75A; TJmax_C: 150°C; U/M: EA; Value: 40V; SizeZ_mm: 1; SizeX_mm: 2.7; SizeY_mm: 1.35; Vf_V: 740mV; Value2: 0.74V; SizeArea_mm2: 3.645; AEC Qualified: Y; AEC Category: Q101
F1 F2 = CMP-0077200-3: Fuse, 30 A, 250 VAC, 100 VDC, SMD; Manufacturer: Littelfuse; VAC_V: 250V; SizeAreaWB_mm2: 61.952; Rtyp_Ohm: 1.93m; SizeArea_mm2: 31.512; MeltingTyp: 916; Irating_A: 30A; SizeZ_mm: 3.12; VDC_V: 100V; SizeX_mm: 10.1; Interrupt_AC: 100A; Interrupt_DC: 50A; Fuse Speed: Fast; Fuse Technology: Board Mount; TaMax_C: 125°C; TaMin_C: -55°C
J1 = CMP-77940-000002-1: CONN HEADER VERT 3POS 2.54MM; Manufacturer: Metz Connect; Conn Orientation: Straight; Current Rating: 3A; Number Of Contacts: 3; Conn Gender: Male
J2 = CMP-0075595-1: Header, 2.54mm, 8x2, Gold, SMT; Manufacturer: Samtec; Pitch_mm: 2.54; Gender: Male; Cert_CSA: Y; Current_A: 4.9A; Voltage_V: 475V; CT: False; Shrouded: N; Row_Count: 2; CNHeader: True
J3 J8 J9 = CMP-0055418-2: Banana Jack Insul Nylon Red, R/A, TH; Manufacturer: Cal Test Electronics; CNHeader: FALSE; Current_A: 25A; Gender: Female; Voltage_V: 1kV; Row_Count: 1; ContactFinish: Nickel; CT: TRUE; Cert_UL: Y
J4 = CMP-0054586-1: Header, 2.54 mm, 12x1, Gold, TH; Manufacturer: Sullins Connector Solutions; CNHeader: TRUE; Current_A: 3A; Shrouded: N; Gender: Male; Voltage_V: 1.8kV; Row_Count: 1; Pitch_mm: 2.54; CT: FALSE; Cert_UL: Y
J10-J12 = CMP-0055598-2: Header, 2.54mm, 5x2, Gold, SMT; Manufacturer: Samtec; Current_A: 5.4A; Green_Lifecycle: Active; Shrouded: N; Gender: Male; Cert_CSA: Y; Green_REACh: Passed; Voltage_V: 475V; Row_Count: 2; RowSpacing_mm: 2.54
J13 = CMP-0079534-2: Header, 2.54mm, 3x2, Gold, SMT; Manufacturer: Wurth Elektronik; Pitch_mm: 2.54; Gender: Male; Cert_UL: Y; Current_A: 3A; Voltage_V: 250V; Shrouded: N; Row_Count: 2
J14 = CMP-0086764-1: Manufacturer: Wurth; Current_A: 57A; Voltage_V: 750V; ContactFinish: Zinc; Row_Count: 1
J15 = CMP-0075110-1: 1mm Uninsulated Shorting Plug, 10.16mm spacing, TH; Manufacturer: Harwin; CNHeader: False; Green_Lifecycle: Active; Green_REACh: Passed; CompType: Jumper Wire
J17 = CMP-0055417-1: Banana Jack Insul Nylon Black, R/A, TH; Manufacturer: Cal Test Electronics; CNHeader: FALSE; Current_A: 25A; Gender: Female; Voltage_V: 1kV; Row_Count: 1; ContactFinish: Nickel; CT: TRUE; Cert_UL: Y
L1 = CMP-0226-00123-1: SMD High Current Cube Inductor WE-HCC, L=1.00 µH; Inductance: 1.00 ÂµH
Q1 = CMP-0000714-1: MOSFET, N-CH, 40 V, 100 A, DQJ0008A (VSONP-8); Alternate Manufacturer: None; Manufacturer: Texas Instruments; SizeZ_mm: 1.1; ChType: N; Value2: 47 nC; Value1: 0.004; VdsMax_V: 40V; SizeX_mm: 6; SizeAreaWB_mm2: 55.2; SizeY_mm: 4.9; Vgs_V: 20V; QgTyp_nC: 47; Value: 40V; Rdson45_ohm: 4.1m; SizeArea_mm2: 29.4; AEC Category: Q101; IdsMax_A: 100A; U/M: EA
R1 R68 = CMP-0025886-3: RES, 10 k, 5%, 0.1 W, 0603; Manufacturer: Yageo America; Power_W: 100mW; TempCo: 100 ppm/C; Value_Code: 10k0; U/M: EA; Value: 10k; EIA_Code: E24; SizeX_mm: 1.6; SizeY_mm: 0.8; SizeZ_mm: 1; Value2: 0.1W; SizeArea_mm2: 1.28; VDC_V: 50V; AEC Category: Q200
R2 R3 R20 = CMP-0025785-4: RES, 330, 5%, 0.1 W, AEC-Q200 Grade 0, 0603; PartNumber: CRCW0603330RJNEA; Manufacturer: Vishay-Dale; CompType: Resistor; Value: 330; Value_Code: 330R; Power_W: 100mW; Value2: 0.1W; VDC_V: 75V; TempCo: 200 ppm/C; EIA_Code: E24; AEC Category: Q200; AEC Qualified: Y; AEC Grade: 0; SizeX_mm: 1.6; SizeY_mm: 0.8; SizeZ_mm: 1; SizeArea_mm2: 1.28
R4 = CMP-0082533-1: RES, 4.99 k, 1%, 0.1 W, 0603; Manufacturer: Vishay-Dale; CompType: Resistor; Value: 4.99k; Value_Code: 4k99; Power_W: 100mW; Value2: 0.1W; VDC_V: 75V; TempCo: 100 ppm/C; EIA_Code: E96; AEC Category: Q200; AEC Qualified: N; SizeAreaWB_mm2: 4.68; SizeX_mm: 1.6; SizeY_mm: 0.8; SizeZ_mm: 1; SizeArea_mm2: 1.28
R5 = CMP-0023129-5: RES, 470, 1%, 0.1 W, 0603; Manufacturer: Yageo; Power_W: 100mW; TempCo: 100 ppm/C; Value_Code: 470R; Value: 470; SizeX_mm: 1.6; SizeY_mm: 0.8; SizeZ_mm: 1; Value2: 0.1W; SizeArea_mm2: 1.28; AEC Qualified: N; VDC_V: 75V; AEC Category: Q200; SizeAreaWB_mm2: 4.68
R6 = CMP-0023235-5: RES, 680, 1%, 0.1 W, 0603; Manufacturer: Yageo; Power_W: 100mW; TempCo: 100 ppm/C; Value_Code: 680R; Value: 680; SizeX_mm: 1.6; SizeY_mm: 0.8; SizeZ_mm: 1; Value2: 0.1W; SizeArea_mm2: 1.28; AEC Qualified: N; VDC_V: 75V; AEC Category: Q200; SizeAreaWB_mm2: 4.68
R7 = CMP-0022895-5: RES, 1.00 k, 1%, 0.1 W, 0603; Manufacturer: Yageo; Power_W: 100mW; TempCo: 100 ppm/C; Value_Code: 1k00; Value: 1.00k; EIA_Code: E96; Res_ohm: 1k; SizeX_mm: 1.6; SizeY_mm: 0.8; SizeZ_mm: 1; Value2: 0.1W; SizeArea_mm2: 1.28; AEC Qualified: N; VDC_V: 75V; AEC Category: Q200; SizeAreaWB_mm2: 4.68
R8 = CMP-0022883-5: RES, 1.50 k, 1%, 0.1 W, 0603; Manufacturer: Yageo; Power_W: 100mW; TempCo: 100 ppm/C; Value_Code: 1k50; Value: 1.50k; EIA_Code: E96; Res_ohm: 1.5k; SizeX_mm: 1.6; SizeY_mm: 0.8; SizeZ_mm: 1; Value2: 0.1W; SizeArea_mm2: 1.28; AEC Qualified: N; VDC_V: 75V; AEC Category: Q200; SizeAreaWB_mm2: 4.68
R9 = CMP-0022986-5: RES, 2.20 k, 1%, 0.1 W, 0603; Manufacturer: Yageo; Power_W: 100mW; TempCo: 100 ppm/C; Value_Code: 2k20; Value: 2.20k; Res_ohm: 2.2k; SizeX_mm: 1.6; SizeY_mm: 0.8; SizeZ_mm: 1; Value2: 0.1W; SizeArea_mm2: 1.28; AEC Qualified: N; VDC_V: 75V; AEC Category: Q200; SizeAreaWB_mm2: 4.68
R10 = CMP-0023081-5: RES, 3.30 k, 1%, 0.1 W, 0603; Manufacturer: Yageo; Power_W: 100mW; TempCo: 100 ppm/C; Value_Code: 3k30; Value: 3.30k; Res_ohm: 3.3k; SizeX_mm: 1.6; SizeY_mm: 0.8; SizeZ_mm: 1; Value2: 0.1W; SizeArea_mm2: 1.28; AEC Qualified: N; VDC_V: 75V; AEC Category: Q200; SizeAreaWB_mm2: 4.68
R11 = CMP-0023153-5: RES, 4.70 k, 1%, 0.1 W, 0603; Manufacturer: Yageo; Power_W: 100mW; TempCo: 100 ppm/C; Value_Code: 4k70; Value: 4.70k; Res_ohm: 4.7k; SizeX_mm: 1.6; SizeY_mm: 0.8; SizeZ_mm: 1; Value2: 0.1W; SizeArea_mm2: 1.28; AEC Qualified: N; VDC_V: 75V; AEC Category: Q200; SizeAreaWB_mm2: 4.68
R12 = CMP-0023253-5: RES, 6.80 k, 1%, 0.1 W, 0603; Manufacturer: Yageo; Power_W: 100mW; TempCo: 100 ppm/C; Value_Code: 6k80; Value: 6.80k; Res_ohm: 6.8k; SizeX_mm: 1.6; SizeY_mm: 0.8; SizeZ_mm: 1; Value2: 0.1W; SizeArea_mm2: 1.28; AEC Qualified: N; VDC_V: 75V; AEC Category: Q200; SizeAreaWB_mm2: 4.68
R13-R17 R39 R40 R52 = CMP-0086358-1: RES, 0, 0%, 0.25 W, AEC-Q200 Grade 0, 0603; Manufacturer: Rohm; Power_W: 250mW; SizeZ_mm: 1; SizeArea_mm2: 1.28; Value2: 0.25W; SizeAreaWB_mm2: 4.68; Value_Code: 0000; Value: 0; AEC Qualified: Y; AEC Category: Q200; SizeX_mm: 1.6; SizeY_mm: 0.8
R18 = CMP-0025925-5: RES, 47 k, 5%, 0.1 W, 0603; Manufacturer: Yageo; Power_W: 100mW; TempCo: 100 ppm/C; Value_Code: 47k0; Value: 47k; EIA_Code: E24; SizeX_mm: 1.6; SizeY_mm: 0.8; SizeZ_mm: 1; Value2: 0.1W; SizeArea_mm2: 1.28; AEC Qualified: N; VDC_V: 75V; AEC Category: Q200; SizeAreaWB_mm2: 4.68
R19 R22-R31 = CMP-2000-03817-1: Manufacturer: Vishay Dale
R21 R67 R69-R72 = CMP-0025886-5: RES, 10 k, 5%, 0.1 W, 0603; Manufacturer: Yageo; Power_W: 100mW; TempCo: 100 ppm/C; Value_Code: 10k0; Value: 10k; EIA_Code: E24; SizeX_mm: 1.6; SizeY_mm: 0.8; SizeZ_mm: 1; Value2: 0.1W; SizeArea_mm2: 1.28; AEC Qualified: N; VDC_V: 75V; AEC Category: Q200; SizeAreaWB_mm2: 4.68
R53-R56 = CMP-0025862-3: RES, 8.2 k, 5%, 0.1 W, 0603; Manufacturer: Vishay-Dale; Power_W: 100mW; TempCo: 200 ppm/C; Value_Code: 8k20; U/M: EA; Value: 8.2k; EIA_Code: E24; SizeX_mm: 1.6; SizeY_mm: 0.8; SizeZ_mm: 1; Value2: 0.1W; SizeArea_mm2: 1.28; VDC_V: 75V; AEC Category: Q200
R57-R59 = CMP-0025757-4: RES, 22 k, 5%, 0.1 W, AEC-Q200 Grade 0, 0603; Manufacturer: Vishay-Dale; Power_W: 100mW; TempCo: 200 ppm/C; Value_Code: 22k0; Value: 22k; EIA_Code: E24; SizeX_mm: 1.6; SizeY_mm: 0.8; SizeZ_mm: 1; Value2: 0.1W; SizeArea_mm2: 1.28; AEC Qualified: Y; VDC_V: 75V; AEC Category: Q200; AEC Grade: 0
R60 = CMP-0025860-2: RES, 82 k, 5%, 0.1 W, 0603; Manufacturer: Vishay-Dale; Power_W: 100mW; TempCo: 200 ppm/C; Value_Code: 82k0; U/M: EA; Value: 82k; EIA_Code: E24; SizeX_mm: 1.6; SizeY_mm: 0.8; SizeZ_mm: 1; Value2: 0.1W; SizeArea_mm2: 1.28; VDC_V: 75V; AEC Category: Q200
R61-R63 = CMP-0022438-1: RES, 47.0 k, 1%, 0.1 W, AEC-Q200 Grade 0, 0603; Manufacturer: Vishay-Dale; Power_W: 100mW; TempCo: 100 ppm/C; Value_Code: 47k0; U/M: EA; Value: 47.0k; Res_ohm: 47k; SizeX_mm: 1.6; SizeY_mm: 0.8; SizeZ_mm: 1; Value2: 0.1W; SizeArea_mm2: 1.28; AEC Qualified: Y; VDC_V: 75V; AEC Grade: 0; AEC Category: Q200
R64-R66 = CMP-0086261-1: RES, 100 k, 0.5%, 0.1 W, AEC-Q200 Grade 0, 0603; Manufacturer: Vishay-Dale; EIA_Code: E192; SizeZ_mm: 1; Power_W: 100mW; Value2: 0.1W; Value: 100k; SizeAreaWB_mm2: 4.68; AEC Qualified: Y; TempCo: 50 ppm/C; SizeArea_mm2: 1.28; AEC Category: Q200; SizeX_mm: 1.6; SizeY_mm: 0.8; AEC Grade: 0
S1 = CMP-0002134-3: Switch, Tactile, SPST-NO, 0.05A, 12V, SMT; Manufacturer: TE Connectivity; CurrentRating_mA: 50A; PositionCount: 1; SwitchFunction: Off-Mom
SH-J1 = CMP-0003677-2: Shunt, 100mil, Gold plated, Black; Manufacturer: TE Connectivity
SH-J2-SH-J6 = CMP-0003761-2: Shunt, 2.54mm, Gold, Black; Manufacturer: Wurth Elektronik
TP1 TP2 TP5 TP6 = CMP-0055152-1: Test Point, Miniature, SMT; Manufacturer: Keystone; CNHeader: FALSE; Green_Lifecycle: Active; Green_REACh: Passed; CT: TRUE
TP3 = CMP-0003719-1: Testpoint; Manufacturer: Texas Instruments; CompType: Pad
TP8 = CMP-0055147-1: Test Point, Multipurpose, Red, TH; Manufacturer: Keystone; CNHeader: FALSE; Green_Lifecycle: Active; Green_REACh: Passed; ContactFinish: Silver; CT: TRUE
TP9 = CMP-0055148-1: Test Point, Multipurpose, Black, TH; Manufacturer: Keystone; CNHeader: FALSE; Green_Lifecycle: Active; Green_REACh: Passed; ContactFinish: Silver; CT: TRUE
U1 = DRV8245S-Q1-HTSSOP-28: DRV8245S-Q1 HTSSOP 28-pin leaded package; Manufacturer: Used in BOM report; CompType: Used in some BOM reports.  Useful for finding later.
U2 = CMP-0070570-1: Ultra-Low Quiescent Current Voltage Regulator, 8-pin Narrow SOIC, Pb-Free; Manufacturer: Texas Instruments; PackageTopMarking: NSZXTT*LM903*6M-3; PowerWise: N; CompType: LDO IC
U3 = CMP-0365-00685-2: 16 MHz Mixed Signal Microcontroller with 16 KB Flash, 512 B SRAM and 24 GPIOs, -40 to 85 degC, 28-pin SOP (PW), Green (RoHS & no Sb/Br); Manufacturer: Texas Instruments; Timers - 16-bit: 2; Watchdog: Yes; GPIO: 24; SRAM(B): 512; Frequency(MHz): 16; USCI_B (I2C & SPI): 1; SubFamily: Value Line; ADC Channels: 8; ADC: 10-bit SAR
U4 = CMP-0076397-2: Zero Iq Reverse Polarity Protection Smart Diode Controller, DGK0008A (VSSOP-8); Manufacturer: Texas Instruments; SizeAreaWB_mm2: 23.6; SizeArea_mm2: 14.7; SizeZ_mm: 1.1; Green_REACh: Passed; SizeY_mm: 3; Green_Lifecycle: Active; CompType: IC; SizeX_mm: 4.9; AEC Category: Q200; AEC Qualified: Y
